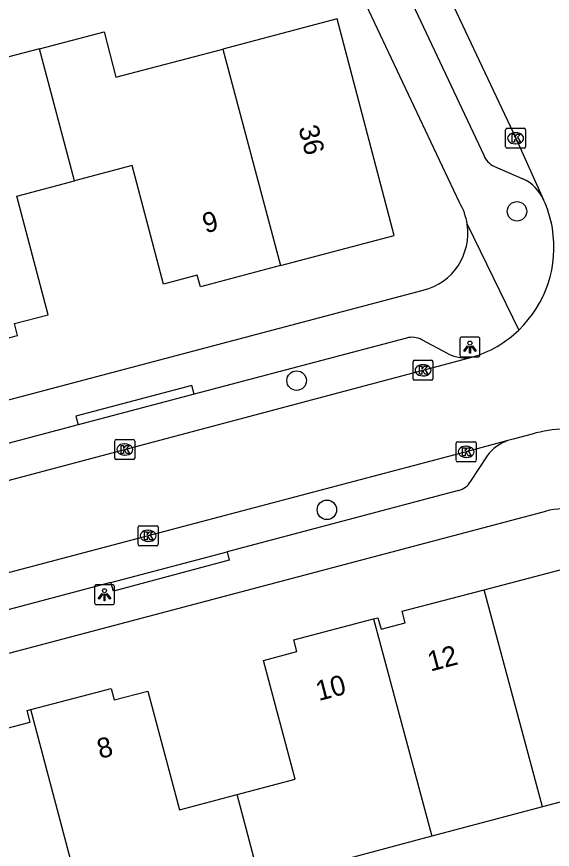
# Model space of a CAD drawing. Extents: x 162880 to 165536, y 384011 to 385179.
# Drawn here: x 163845.34 to 163872.2, y 384364.8 to 384406.52 of the extents above; entities that cross this region are included whole.
import ezdxf

# ---------------------------------------------------------------- set-up
doc = ezdxf.new("R2010")
doc.units = 0
for name, color, linetype in [('IMGEO_Boom', 7, 'Continuous'), ('IMGEO_Kolk', 7, 'Continuous'), ('IMGEO_Lichtpunt', 7, 'Continuous'), ('IMGEO_Pand', 7, 'Continuous'), ('IMGEO_Pand_nummerreeks', 7, 'Continuous'), ('IMGEO_Rijbaan_lokaal_gesloten', 7, 'Continuous'), ('IMGEO_Rijbaan_lokaal_open', 7, 'Continuous'), ('IMGEO_Voetpad_open', 7, 'Continuous')]:
    doc.layers.add(name, color=color, linetype=linetype)

msp = doc.modelspace()

# ---------------------------------------------------------------- linework, layer by layer
at = {"layer": 'IMGEO_Boom'}
for centre in [(163870.425, 384396.763), (163859.377, 384388.284), (163860.895, 384381.811)]:
    msp.add_circle(centre, 0.489, dxfattribs=at)
at = {"layer": 'IMGEO_Kolk'}
for p, q in [((163869.856, 384399.998), (163869.856, 384400.85)), ((163869.931, 384400.924), (163870.783, 384400.924)), ((163870.344, 384400.704), (163870.369, 384400.704)), ((163870.857, 384400.85), (163870.857, 384399.998)), ((163870.783, 384399.924), (163869.931, 384399.924)), ((163870.367, 384400.144), (163870.342, 384400.144)), ((163865.212, 384388.375), (163865.212, 384389.227)), ((163865.287, 384389.301), (163866.139, 384389.301)), ((163865.7, 384389.081), (163865.725, 384389.081)), ((163866.213, 384389.227), (163866.213, 384388.375)), ((163865.723, 384388.521), (163865.698, 384388.521)), ((163866.139, 384388.301), (163865.287, 384388.301)), ((163850.261, 384384.405), (163850.261, 384385.257)), ((163850.336, 384385.331), (163851.188, 384385.331)), ((163851.262, 384385.257), (163851.262, 384384.405)), ((163867.452, 384385.215), (163868.304, 384385.215)), ((163850.749, 384385.111), (163850.774, 384385.111)), ((163867.377, 384384.289), (163867.377, 384385.141)), ((163867.865, 384384.995), (163867.89, 384384.995)), ((163868.378, 384385.141), (163868.378, 384384.289)), ((163850.772, 384384.551), (163850.747, 384384.551)), ((163867.888, 384384.435), (163867.863, 384384.435)), ((163851.188, 384384.331), (163850.336, 384384.331)), ((163868.304, 384384.215), (163867.452, 384384.215)), ((163851.51, 384381.007), (163852.362, 384381.007)), ((163851.435, 384380.081), (163851.435, 384380.933)), ((163851.923, 384380.787), (163851.948, 384380.787)), ((163852.436, 384380.933), (163852.436, 384380.081)), ((163851.946, 384380.227), (163851.921, 384380.227)), ((163852.362, 384380.007), (163851.51, 384380.007))]:
    msp.add_line(p, q, dxfattribs=at)
for points in [[(163869.856, 384399.998), (163869.856, 384400.85)], [(163869.931, 384400.924), (163870.783, 384400.924)], [(163870.177, 384400.624), (163870.3, 384400.624), (163870.3, 384400.473), (163870.43, 384400.624), (163870.594, 384400.624), (163870.448, 384400.473), (163870.601, 384400.224), (163870.449, 384400.224), (163870.364, 384400.388), (163870.3, 384400.321), (163870.3, 384400.224), (163870.177, 384400.224), (163870.177, 384400.624)], [(163870.857, 384400.85), (163870.857, 384399.998)], [(163870.783, 384399.924), (163869.931, 384399.924)], [(163865.212, 384388.375), (163865.212, 384389.227)], [(163865.287, 384389.301), (163866.139, 384389.301)], [(163865.533, 384389.001), (163865.656, 384389.001), (163865.656, 384388.85), (163865.786, 384389.001), (163865.95, 384389.001), (163865.804, 384388.85), (163865.957, 384388.601), (163865.805, 384388.601), (163865.72, 384388.765), (163865.656, 384388.698), (163865.656, 384388.601), (163865.533, 384388.601), (163865.533, 384389.001)], [(163866.213, 384389.227), (163866.213, 384388.375)], [(163866.139, 384388.301), (163865.287, 384388.301)], [(163850.261, 384384.405), (163850.261, 384385.257)], [(163850.336, 384385.331), (163851.188, 384385.331)], [(163851.262, 384385.257), (163851.262, 384384.405)], [(163867.452, 384385.215), (163868.304, 384385.215)], [(163850.582, 384385.031), (163850.705, 384385.031), (163850.705, 384384.88), (163850.835, 384385.031), (163850.999, 384385.031), (163850.853, 384384.88), (163851.006, 384384.631), (163850.854, 384384.631), (163850.769, 384384.795), (163850.705, 384384.728), (163850.705, 384384.631), (163850.582, 384384.631), (163850.582, 384385.031)], [(163867.377, 384384.289), (163867.377, 384385.141)], [(163867.698, 384384.915), (163867.821, 384384.915), (163867.821, 384384.764), (163867.951, 384384.915), (163868.115, 384384.915), (163867.969, 384384.764), (163868.122, 384384.515), (163867.97, 384384.515), (163867.885, 384384.679), (163867.821, 384384.612), (163867.821, 384384.515), (163867.698, 384384.515), (163867.698, 384384.915)], [(163868.378, 384385.141), (163868.378, 384384.289)], [(163851.188, 384384.331), (163850.336, 384384.331)], [(163868.304, 384384.215), (163867.452, 384384.215)], [(163851.51, 384381.007), (163852.362, 384381.007)], [(163851.435, 384380.081), (163851.435, 384380.933)], [(163851.756, 384380.707), (163851.879, 384380.707), (163851.879, 384380.556), (163852.009, 384380.707), (163852.173, 384380.707), (163852.027, 384380.556), (163852.18, 384380.307), (163852.028, 384380.307), (163851.943, 384380.471), (163851.879, 384380.404), (163851.879, 384380.307), (163851.756, 384380.307), (163851.756, 384380.707)], [(163852.436, 384380.933), (163852.436, 384380.081)], [(163852.362, 384380.007), (163851.51, 384380.007)]]:
    msp.add_lwpolyline(points, dxfattribs=at)
for centre, start, end in [((163869.933, 384400.848), 91.552, 178.448), ((163869.933, 384400.848), 91.552, 178.448), ((163870.781, 384400.848), 1.552, 88.448), ((163870.781, 384400.848), 1.552, 88.448), ((163869.933, 384400), 181.552, 268.448), ((163869.933, 384400), 181.552, 268.448), ((163870.781, 384400), 271.552, 358.448), ((163870.781, 384400), 271.552, 358.448), ((163865.289, 384389.225), 91.552, 178.448), ((163865.289, 384389.225), 91.552, 178.448), ((163866.137, 384389.225), 1.552, 88.448), ((163866.137, 384389.225), 1.552, 88.448), ((163865.289, 384388.377), 181.552, 268.448), ((163865.289, 384388.377), 181.552, 268.448), ((163866.137, 384388.377), 271.552, 358.448), ((163866.137, 384388.377), 271.552, 358.448), ((163850.338, 384385.255), 91.552, 178.448), ((163850.338, 384385.255), 91.552, 178.448), ((163851.186, 384385.255), 1.552, 88.448), ((163851.186, 384385.255), 1.552, 88.448), ((163867.454, 384385.139), 91.552, 178.448), ((163867.454, 384385.139), 91.552, 178.448), ((163868.302, 384385.139), 1.552, 88.448), ((163868.302, 384385.139), 1.552, 88.448), ((163850.338, 384384.407), 181.552, 268.448), ((163850.338, 384384.407), 181.552, 268.448), ((163851.186, 384384.407), 271.552, 358.448), ((163851.186, 384384.407), 271.552, 358.448), ((163867.454, 384384.291), 181.552, 268.448), ((163867.454, 384384.291), 181.552, 268.448), ((163868.302, 384384.291), 271.552, 358.448), ((163868.302, 384384.291), 271.552, 358.448), ((163851.512, 384380.931), 91.552, 178.448), ((163851.512, 384380.931), 91.552, 178.448), ((163852.36, 384380.931), 1.552, 88.448), ((163852.36, 384380.931), 1.552, 88.448), ((163851.512, 384380.083), 181.552, 268.448), ((163851.512, 384380.083), 181.552, 268.448), ((163852.36, 384380.083), 271.552, 358.448), ((163852.36, 384380.083), 271.552, 358.448)]:
    msp.add_arc(centre, 0.0765, start, end, dxfattribs=at)
for centre, major_axis, ratio, start_param, end_param in [((163870.343, 384400.424), (-0.387, 0.002), 0.722429, 4.712389, 7.853982), ((163870.368, 384400.424), (-0.39, 0.002), 0.717154, 1.570796, 4.712389), ((163865.699, 384388.801), (-0.387, 0.002), 0.722429, 4.712389, 7.853982), ((163865.724, 384388.801), (-0.39, 0.002), 0.717154, 1.570796, 4.712389), ((163850.748, 384384.831), (-0.387, 0.002), 0.722429, 4.712389, 7.853982), ((163850.773, 384384.831), (-0.39, 0.002), 0.717154, 1.570796, 4.712389), ((163867.864, 384384.715), (-0.387, 0.002), 0.722429, 4.712389, 7.853982), ((163867.889, 384384.715), (-0.39, 0.002), 0.717154, 1.570796, 4.712389), ((163851.922, 384380.507), (-0.387, 0.002), 0.722429, 4.712389, 7.853982), ((163851.947, 384380.507), (-0.39, 0.002), 0.717154, 1.570796, 4.712389)]:
    msp.add_ellipse(centre, major_axis=major_axis, ratio=ratio, start_param=start_param, end_param=end_param, dxfattribs=at)
at = {"layer": 'IMGEO_Lichtpunt'}
for p, q in [((163867.566, 384390.368), (163867.566, 384389.561)), ((163867.566, 384390.368), (163867.566, 384389.561)), ((163868.468, 384390.463), (163867.66, 384390.463)), ((163868.468, 384390.463), (163867.66, 384390.463)), ((163868.562, 384389.561), (163868.562, 384390.368)), ((163868.562, 384389.561), (163868.562, 384390.368)), ((163867.66, 384389.467), (163868.468, 384389.467)), ((163867.66, 384389.467), (163868.468, 384389.467)), ((163849.248, 384377.96), (163849.248, 384377.153)), ((163849.248, 384377.96), (163849.248, 384377.153)), ((163850.15, 384378.055), (163849.342, 384378.055)), ((163850.15, 384378.055), (163849.342, 384378.055)), ((163850.244, 384377.153), (163850.244, 384377.96)), ((163850.244, 384377.153), (163850.244, 384377.96)), ((163849.342, 384377.059), (163850.15, 384377.059)), ((163849.342, 384377.059), (163850.15, 384377.059))]:
    msp.add_line(p, q, dxfattribs=at)
for points in [[(163867.94, 384390.032), (163867.979, 384390.004), (163867.791, 384389.742), (163867.753, 384389.769), (163867.94, 384390.032)], [(163868.042, 384389.984), (163868.089, 384389.984), (163868.089, 384389.662), (163868.042, 384389.662), (163868.042, 384389.984)], [(163868.152, 384390.004), (163868.19, 384390.031), (163868.377, 384389.769), (163868.338, 384389.741), (163868.152, 384390.004)], [(163849.622, 384377.624), (163849.661, 384377.596), (163849.473, 384377.334), (163849.435, 384377.361), (163849.622, 384377.624)], [(163849.724, 384377.576), (163849.771, 384377.576), (163849.771, 384377.254), (163849.724, 384377.254), (163849.724, 384377.576)], [(163849.834, 384377.596), (163849.872, 384377.623), (163850.059, 384377.361), (163850.02, 384377.333), (163849.834, 384377.596)]]:
    msp.add_lwpolyline(points, dxfattribs=at)
for centre in [(163868.065, 384390.166), (163849.747, 384377.758)]:
    msp.add_circle(centre, 0.0994, dxfattribs=at)
for centre, start, end in [((163867.66, 384390.368), 90, 180), ((163867.66, 384390.368), 90, 180), ((163868.468, 384390.368), 0, 90), ((163868.468, 384390.368), 0, 90), ((163867.66, 384389.561), 180, 270), ((163867.66, 384389.561), 180, 270), ((163868.468, 384389.561), 270, 0), ((163868.468, 384389.561), 270, 360), ((163849.342, 384377.96), 90, 180), ((163849.342, 384377.96), 90, 180), ((163850.15, 384377.96), 0, 90), ((163850.15, 384377.96), 0, 90), ((163849.342, 384377.153), 180, 270), ((163849.342, 384377.153), 180, 270), ((163850.15, 384377.153), 270, 0), ((163850.15, 384377.153), 270, 360)]:
    msp.add_arc(centre, 0.0946, start, end, dxfattribs=at)
at = {"layer": 'IMGEO_Pand'}
for points in [[(163858.577, 384394.046), (163864.267, 384395.554), (163861.414, 384406.402), (163855.685, 384404.895)], [(163846.484, 384404.902), (163849.725, 384405.759), (163850.322, 384403.485), (163855.685, 384404.895)], [(163846.484, 384404.902), (163844.892, 384404.481), (163841.103, 384403.478), (163841.699, 384401.225), (163838.461, 384400.366)], [(163848.238, 384398.285), (163846.484, 384404.902)], [(163855.685, 384404.895), (163858.577, 384394.046)], [(163858.577, 384394.046), (163854.553, 384392.979), (163854.397, 384393.569), (163852.711, 384393.107), (163851.14, 384399.053), (163848.238, 384398.285)], [(163841.393, 384389.491), (163845.392, 384390.551), (163845.236, 384391.141), (163846.918, 384391.573), (163845.347, 384397.519), (163848.238, 384398.285)], [(163868.771, 384377.805), (163874.486, 384379.311), (163877.359, 384368.434), (163871.695, 384366.927)], [(163863.228, 384376.343), (163863.455, 384376.403), (163863.608, 384375.823), (163864.827, 384376.144), (163864.674, 384376.725), (163868.771, 384377.805)], [(163871.695, 384366.927), (163868.771, 384377.805)], [(163856.396, 384367.552), (163859.302, 384368.319), (163857.713, 384374.261), (163859.394, 384374.711), (163859.239, 384375.291), (163863.228, 384376.343)], [(163863.228, 384376.343), (163866.155, 384365.453)], [(163846.054, 384371.801), (163850.085, 384372.866), (163850.239, 384372.286), (163851.923, 384372.725), (163853.501, 384366.787), (163856.396, 384367.552)], [(163840.521, 384370.34), (163844.652, 384371.431), (163844.806, 384370.851), (163846.024, 384371.173), (163845.87, 384371.752), (163846.054, 384371.801)], [(163848.944, 384360.897), (163846.054, 384371.801)], [(163858.155, 384360.919), (163856.396, 384367.552)], [(163871.695, 384366.927), (163866.155, 384365.453)], [(163866.155, 384365.453), (163860.788, 384364.025), (163861.383, 384361.772), (163858.155, 384360.919)]]:
    msp.add_lwpolyline(points, dxfattribs=at)
at = {"layer": 'IMGEO_Rijbaan_lokaal_gesloten'}
msp.add_lwpolyline([(163851.333, 384440.761), (163852.509, 384438.313), (163860.778, 384420.748), (163870.358, 384400.425), (163871.755, 384397.347)], dxfattribs=at)
msp.add_arc((163866.524, 384394.95), 5.754, 9.6229, 24.6162, dxfattribs=at)
at = {"layer": 'IMGEO_Rijbaan_lokaal_open'}
for points in [[(163823.263, 384378.046), (163826.557, 384378.434), (163834.844, 384380.604), (163865.713, 384388.799), (163868.168, 384389.455)], [(163871.192, 384385.606), (163870.228, 384385.351), (163869.972, 384385.282)], [(163869.972, 384385.282), (163867.877, 384384.716), (163851.935, 384380.508), (163835.992, 384376.295), (163828.118, 384374.191), (163827.488, 384374.039), (163824.303, 384373.665)]]:
    msp.add_lwpolyline(points, dxfattribs=at)
for centre, radius, start, end in [((163866.542, 384394.954), 5.735, 313.83, 9.6108), ((163866.551, 384394.943), 5.721, 286.4233, 313.8524), ((163873.017, 384379.327), 6.538, 91.9327, 106.2033)]:
    msp.add_arc(centre, radius, start, end, dxfattribs=at)
at = {"layer": 'IMGEO_Voetpad_open'}
for points in [[(163860.646, 384416.805), (163868.76, 384399.572)], [(163867.54, 384397.202), (163862.998, 384406.819), (163858.657, 384416.012)], [(163869.291, 384399.012), (163870.723, 384398.394)], [(163867.929, 384396.122), (163870.514, 384390.817)], [(163802.92, 384378.611), (163816.096, 384380.674), (163825.065, 384382.078), (163825.148, 384382.091), (163865.727, 384392.809)], [(163864.892, 384390.413), (163854.243, 384387.611)], [(163866.981, 384389.631), (163865.652, 384390.328)], [(163854.243, 384387.611), (163854.132, 384388.038), (163848.312, 384386.508), (163848.431, 384386.065)], [(163854.243, 384387.611), (163848.431, 384386.065)], [(163848.431, 384386.065), (163831.487, 384381.581)], [(163868.93, 384384.516), (163868.102, 384383.238)], [(163867.495, 384382.781), (163855.892, 384379.711)], [(163871.845, 384381.733), (163828.311, 384370.22), (163828.207, 384370.211), (163817.519, 384369.317), (163804.137, 384368.197)], [(163850.07, 384378.169), (163855.892, 384379.711)], [(163855.892, 384379.711), (163855.992, 384379.282), (163850.195, 384377.738), (163850.07, 384378.169)], [(163850.07, 384378.169), (163833.614, 384373.811)]]:
    msp.add_lwpolyline(points, dxfattribs=at)
for centre, radius, start, end in [((163869.682, 384399.914), 0.983, 200.3703, 246.5845), ((163869.794, 384396.446), 2.158, 24.6712, 64.5021), ((163865.032, 384395.688), 2.93, 8.5102, 31.1063), ((163865.005, 384395.677), 2.958, 284.1307, 8.6489), ((163865.172, 384389.478), 0.976, 60.5533, 106.6836), ((163867.825, 384391.235), 1.813, 242.2372, 280.8948), ((163870.657, 384383.258), 2.136, 108.7023, 143.9387), ((163867.285, 384383.692), 0.935, 282.99, 330.9609), ((163872.722, 384378.751), 3.109, 43.7677, 106.3877)]:
    msp.add_arc(centre, radius, start, end, dxfattribs=at)

# ---------------------------------------------------------------- texts
at = {"layer": 'IMGEO_Pand_nummerreeks'}
for s, rotation, p in [('36', 284.735, (163859.459, 384400.942)), ('9', 14.8466, (163854.808, 384395.655)), ('12', 14.7594, (163866.09, 384373.704)), ('10', 14.7594, (163860.488, 384372.228)), ('8', 14.7991, (163849.525, 384369.326))]:
    msp.add_text(s, height=1, rotation=rotation, dxfattribs=at).set_placement(p)

doc.saveas('drawing.dxf')
